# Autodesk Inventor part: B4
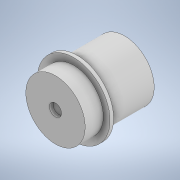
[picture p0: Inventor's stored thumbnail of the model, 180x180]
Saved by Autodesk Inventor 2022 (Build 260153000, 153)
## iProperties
Created: 2024-12
Part Number: B4
Material: 一般
Document SubType Name: Modeling
Designer: jsat7
Density: 1 g/cm^3
Appearance: 既定
Author: jsat7
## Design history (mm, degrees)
sketch "スケッチ1"
  geometry: C1 r 2.45 at (0, 0); 1 further point
  constraints: 1 centre point, 1 coincident
  dimensions: "d0" = 4.9 diameter of C1
extrude "押し出し1" new body sketch "スケッチ1" distance "d1" = 1.5; taper "d2" = 0 deg
sketch "スケッチ2"
  geometry: C1 r 3 at (0, 0); 1 further point
  constraints: 1 centre point, 1 coincident
  dimensions: "d3" = 6 diameter of C1
extrude "押し出し2" join sketch "スケッチ2" distance "d4" = 0.3; taper "d5" = 0 deg
sketch "スケッチ3"
  geometry: C1 r 2.45 at (0, 0); 1 further point
  constraints: 1 centre point, 1 coincident
  dimensions: "d6" = 4.9 diameter of C1
extrude "押し出し3" join sketch "スケッチ3" distance "d7" = 3.9; taper "d8" = 0 deg
sketch "スケッチ4"
  geometry: C1 r 1.5 at (0, 0); 1 further point
  constraints: 1 centre point, 1 coincident
  dimensions: "d9" = 3 diameter of C1
extrude "押し出し4" cut sketch "スケッチ4" distance "d10" = 3.5; taper "d11" = 0 deg
sketch "スケッチ5"
  geometry: C1 r 0.5 at (0, 0); 1 further point
  constraints: 1 centre point, 1 coincident
  dimensions: "d12" = 1 diameter of C1
extrude "押し出し5" cut sketch "スケッチ5" distance "d13" = 0.3; taper "d14" = 0 deg
node "ソリッド1"
